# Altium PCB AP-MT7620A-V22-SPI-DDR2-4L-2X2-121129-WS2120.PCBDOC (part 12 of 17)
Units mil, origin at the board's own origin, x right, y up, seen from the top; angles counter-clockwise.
Board outline 7316 x 4279 mil, 4 copper layers (Top, Inner Layer 2, Inner Layer 3, Bottom), stack 35.4 mil thick; 640 components, 473 nets, 2041 pads, 2358 vias.
Unrouted connection lines stored in the file: 11.
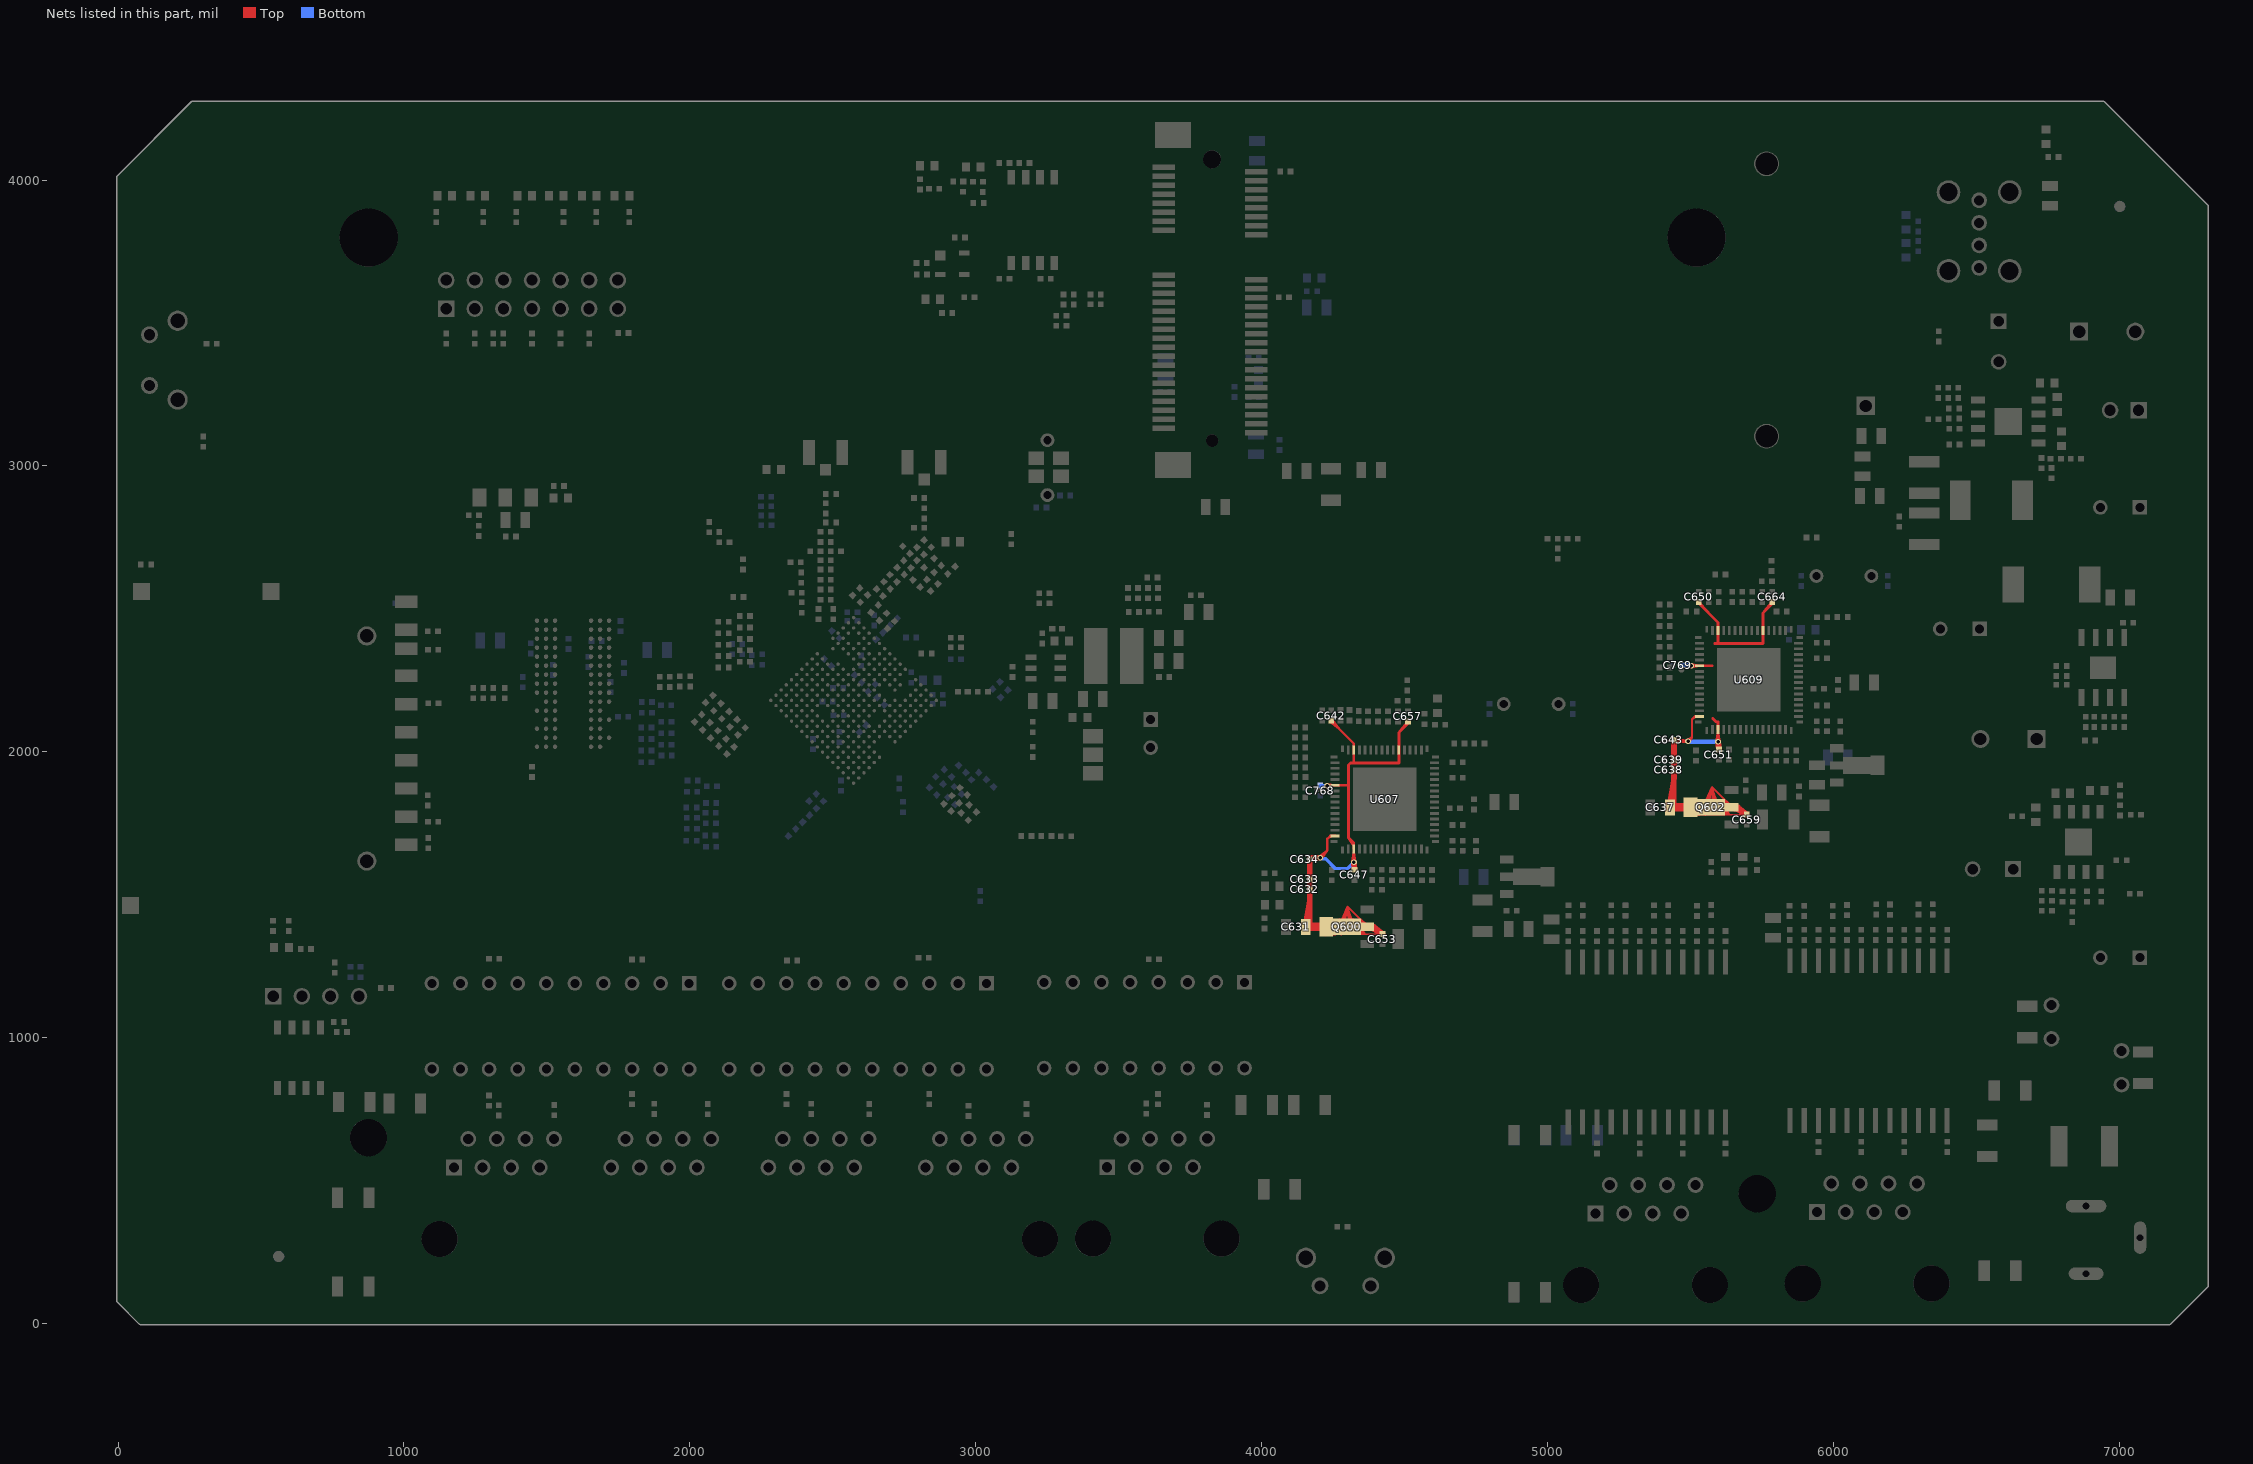
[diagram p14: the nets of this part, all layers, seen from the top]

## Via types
v1: diameter 20, hole 12, Top to Bottom, 2117 vias
v2: diameter 16, hole 8, Top to Bottom, 241 vias

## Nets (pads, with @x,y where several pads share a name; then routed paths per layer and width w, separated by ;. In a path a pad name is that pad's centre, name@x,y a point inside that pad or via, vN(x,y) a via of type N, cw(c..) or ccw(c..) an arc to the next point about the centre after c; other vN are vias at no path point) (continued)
P_DVDD_IP1001: C631.1 C632.1 C633.1 C634.1 C642.1 C647.1 C653.2 C657.1 C768.1 Q600.2 Q600.4 Q600.5 U607.3 U607.38 U607.46 U607.54 U607.63 | length 26663.2
  Top w4: v1@4228.67,1885.43 U607.54@4246.38,1886.13 ; v1@4228.98,1889.47 U607.54@4246.38,1886.13 ; v1@4229.33,1885.48 U607.54@4246.93,1883.26 ; v1@4229.48,1877.48 U607.54@4246.99,1880.34 ; v1@4229.62,1877.49 U607.54@4253.28,1881.48 ; v1@4229.62,1885.46 U607.54@4253.28,1881.48 ; v1@4229.99,1885.42 U607.54@4246.99,1880.34 ; v1@4230.13,1877.57 U607.54@4246.93,1883.26 ; v1@4230.29,1889.41 U607.54@4246.93,1883.26 ; v1@4230.62,1889.37 U607.54@4253.28,1881.48 ; v1@4230.76,1877.76 U607.54@4246.38,1886.13 ; v1@4231.58,1889.14 U607.54@4246.99,1880.34 ; v1@4231.86,1873.91 U607.54@4246.93,1883.26 ; v1@4233.07,1874.43 U607.54@4246.38,1886.13 ; U607.54@4268.53,1880.34 4285.55,1881.48 ; U607.54@4268.59,1883.26 4285.55,1881.48 ; U607.54@4269.14,1886.13 4285.55,1881.48 ; 4301.99,1881.48 v1(4229.28,1881.48) ; v1(4229.28,1881.48) U607.54@4246.99,1880.34 ; v1(4229.28,1881.48) U607.54@4246.38,1886.13 ; v1(4229.28,1881.48) U607.54@4246.93,1883.26 ; v1@4229.99,1881.48 U607.54@4246.99,1880.34 ; v1@4229.99,1881.48 U607.54@4246.38,1886.13 ; v1@4229.99,1881.48 U607.54@4246.93,1883.26 ; U607.54@4246.99,1880.34 4230.58,1873.58 U607.54@4253.28,1881.48
  Top w5: Q600.2@4220.32,1367.38 Q600.5@4274.82,1362.05 ; Q600.2@4221.05,1372.4 Q600.5@4274.82,1362.05 ; Q600.2@4222.23,1377.3 Q600.5@4274.82,1362.05 ; Q600.2@4223.85,1382.05 Q600.5@4274.82,1362.05 ; Q600.5@4259.95,1368.21 Q600.2@4240.45,1404.67 ; Q600.5@4261.05,1408.85 Q600.2@4230.97,1366.34 ; Q600.5@4262.55,1366.09 Q600.2@4236.65,1401.31 ; Q600.5@4262.76,1410.16 Q600.2@4230.08,1370.66 ; Q600.5@4264.4,1370.97 Q600.2@4240.45,1404.67 ; Q600.5@4264.69,1411.4 Q600.2@4229.44,1375.21 ; Q600.5@4265.09,1405.68 Q600.2@4230.97,1366.34 ; Q600.5@4265.19,1364.42 Q600.2@4233.2,1397.63 ; Q600.5@4266.55,1369.42 Q600.2@4236.65,1401.31 ; Q600.5@4266.56,1406.68 Q600.2@4230.08,1370.66 ; Q600.5@4266.87,1412.54 Q600.2@4229.11,1379.99 ; Q600.5@4267.82,1363.14 Q600.2@4230.12,1393.67 ; Q600.5@4268.2,1407.62 Q600.2@4229.44,1375.21 ; Q600.5@4268.4,1374.2 Q600.2@4240.45,1404.67 ; Q600.5@4268.72,1368.22 Q600.2@4233.2,1397.63 ; Q600.5@4268.77,1402.16 Q600.2@4230.97,1366.34 ; Q600.5@4269.95,1402.89 Q600.2@4230.08,1370.66 ; Q600.5@4270.03,1408.46 Q600.2@4229.11,1379.99 ; Q600.5@4270.08,1373.14 Q600.2@4236.65,1401.31 ; Q600.5@4270.13,1413.81 Q600.2@4229.23,1386.65 ; Q600.5@4270.85,1367.32 Q600.2@4230.12,1393.67 ; Q600.5@4271.24,1361.96 Q600.2@4226.63,1388.05 ; Q600.5@4271.26,1403.55 Q600.2@4229.44,1375.21 ; Q600.5@4271.24,1414.14 Q600.2@4226.63,1388.05 ; Q600.5@4271.61,1361.86 Q600.2@4229.23,1386.65 ; Q600.5@4271.58,1393.8 4299.95,1460.55 ; Q600.5@4271.75,1372.33 Q600.2@4233.2,1397.63 ; Q600.5@4271.92,1377.86 Q600.2@4240.45,1404.67 ; Q600.5@4272.06,1398.33 Q600.2@4230.97,1366.34 ; Q600.5@4272.72,1404.14 Q600.2@4229.11,1379.99 ; Q600.5@4272.75,1409.37 Q600.2@4229.23,1386.65 ; Q600.5@4272.93,1398.81 Q600.2@4230.08,1370.66 ; Q600.5@4273.12,1377.2 Q600.2@4236.65,1401.31 ; Q600.5@4273.39,1371.75 Q600.2@4230.12,1393.67 ; Q600.5@4273.61,1409.57 Q600.2@4226.63,1388.05 ; Q600.5@4273.83,1414.71 Q600.2@4230.12,1393.67 ; Q600.5@4273.89,1399.24 Q600.2@4229.44,1375.21 ; Q600.5@4273.98,1366.45 Q600.2@4229.23,1386.65 ; Q600.5@4274.29,1376.71 Q600.2@4233.2,1397.63 ; Q600.5@4274.87,1404.73 Q600.2@4229.23,1386.65 ; Q600.5@4274.94,1381.88 Q600.2@4240.45,1404.67 ; Q600.5@4274.95,1394.23 Q600.2@4230.97,1366.34 ; Q600.5@4274.94,1399.6 Q600.2@4229.11,1379.99 ; Q600.5@4275.28,1361.19 Q600.2@4229.11,1379.99 ; Q600.5@4275.44,1376.37 Q600.2@4230.12,1393.67 ; Q600.5@4275.47,1394.48 Q600.2@4230.08,1370.66 ; Q600.5@4275.5,1371.26 Q600.2@4226.63,1388.05 ; Q600.5@4275.5,1404.84 Q600.2@4226.63,1388.05 ; Q600.5@4275.64,1381.55 Q600.2@4236.65,1401.31 ; Q600.5@4275.82,1409.94 Q600.2@4230.12,1393.67 ; Q600.5@4275.83,1371.2 Q600.2@4229.23,1386.65 ; Q600.5@4275.92,1414.97 Q600.2@4233.2,1397.63 ; Q600.5@4276.05,1394.71 Q600.2@4229.44,1375.21 ; Q600.5@4276.32,1391.98 4299.95,1460.55 ; Q600.5@4276.33,1381.31 Q600.2@4233.2,1397.63 ; Q600.5@4276.49,1399.94 Q600.2@4229.23,1386.65 ; Q600.5@4276.68,1394.89 Q600.2@4229.11,1379.99 ; Q600.5@4276.91,1376.1 Q600.2@4226.63,1388.05 ; Q600.5@4276.91,1400 Q600.2@4226.63,1388.05 ; Q600.5@4276.98,1366.06 Q600.2@4229.11,1379.99 ; Q600.5@4277.28,1405.05 Q600.2@4230.12,1393.67 ; Q600.5@4277.6,1395.04 Q600.2@4229.23,1386.65 ; Q600.5@4277.6,1410.07 Q600.2@4233.2,1397.63 ; Q600.5@4277.83,1381.04 Q600.2@4226.63,1388.05 ; Q600.5@4277.93,1361.03 Q600.2@4229.44,1375.21 ; Q600.5@4278.15,1371.02 Q600.2@4229.11,1379.99 ; Q600.5@4278.14,1415.08 Q600.2@4236.65,1401.31 ; Q600.5@4278.21,1400.08 Q600.2@4230.12,1393.67 ; Q600.5@4278.61,1395.07 Q600.2@4230.12,1393.67 ; Q600.5@4278.71,1405.07 Q600.2@4233.2,1397.63 ; Q600.5@4278.8,1376.03 Q600.2@4229.11,1379.99 ; Q600.5@4278.95,1381.05 Q600.2@4229.11,1379.99 ; Q600.5@4279.12,1366.04 Q600.2@4229.44,1375.21 ; Q600.5@4279.24,1395.02 Q600.2@4233.2,1397.63 ; Q600.5@4279.25,1400.04 Q600.2@4233.2,1397.63 ; Q600.5@4279.48,1410.05 Q600.2@4236.65,1401.31 ; Q600.5@4279.61,1381.15 Q600.2@4229.44,1375.21 ; Q600.5@4279.8,1371.09 Q600.2@4229.44,1375.21 ; Q600.5@4279.89,1394.9 Q600.2@4236.65,1401.31 ; Q600.5@4279.96,1376.14 Q600.2@4229.44,1375.21 ; Q600.5@4280.21,1404.97 Q600.2@4236.65,1401.31 ; Q600.5@4280.23,1381.29 Q600.2@4230.08,1370.66 ; Q600.5@4280.34,1399.9 Q600.2@4236.65,1401.31 ; Q600.5@4280.45,1361.11 Q600.2@4230.08,1370.66 ; Q600.5@4280.49,1414.99 Q600.2@4240.45,1404.67 ; Q600.5@4280.57,1394.7 Q600.2@4240.45,1404.67 ; Q600.5@4280.8,1381.48 Q600.2@4230.97,1366.34 ; Q600.5@4281.03,1376.33 Q600.2@4230.08,1370.66 ; Q600.5@4281.15,1366.21 Q600.2@4230.08,1370.66 ; Q600.5@4281.14,1390.51 4299.95,1460.55 ; Q600.5@4281.34,1371.3 Q600.2@4230.08,1370.66 ; Q600.5@4281.47,1409.85 Q600.2@4240.45,1404.67 ; Q600.5@4281.49,1399.65 Q600.2@4240.45,1404.67 ; Q600.5@4281.79,1404.72 Q600.2@4240.45,1404.67 ; Q600.5@4282.02,1376.61 Q600.2@4230.97,1366.34 ; Q600.5@4282.81,1361.4 Q600.2@4230.97,1366.34 ; Q600.5@4282.78,1371.62 Q600.2@4230.97,1366.34 ; Q600.5@4283.05,1366.54 Q600.2@4230.97,1366.34 ; Q600.5@4286.04,1389.37 4299.95,1460.55 ; Q600.5@4290.98,1388.58 4299.95,1460.55 ; Q600.5@4297.99,1388.05 4302.94,1393 4392.04,1393 4409,1376.04 ; Q600.5@4305.02,1388.2 4299.95,1460.55 ; Q600.5@4310,1388.72 4299.95,1460.55 ; Q600.5@4310.81,1361.91 4363.51,1362.05 ; Q600.5@4311.05,1367.04 4363.51,1362.05 ; Q600.5@4311.78,1372.08 4363.51,1362.05 ; Q600.5@4312.97,1376.98 4363.51,1362.05 ; Q600.5@4314.62,1381.72 4363.51,1362.05 ; Q600.5@4314.95,1389.59 4299.95,1460.55 ; Q600.5@4316.06,1399.97 Q600.4@4359.05,1399.72 ; Q600.5@4316.14,1376.12 Q600.4@4355.24,1377.15 ; Q600.5@4316.33,1381.15 Q600.4@4355.24,1377.15 ; Q600.5@4316.33,1394.95 Q600.4@4359.05,1399.72 ; Q600.5@4316.39,1405.03 Q600.4@4359.05,1399.72 ; Q600.5@4316.6,1371.06 Q600.4@4355.24,1377.15 ; Q600.5@4317.17,1381.04 Q600.4@4357.56,1381.64 ; Q600.5@4317.33,1410.07 Q600.4@4359.05,1399.72 ; Q600.5@4317.39,1400.07 Q600.4@4368.59,1395.25 ; Q600.5@4317.45,1395.07 Q600.4@4362.27,1393 ; Q600.5@4317.49,1400.08 Q600.4@4359.77,1394.71 ; Q600.5@4317.55,1376.02 Q600.4@4357.56,1381.64 ; Q600.5@4317.66,1395.08 Q600.4@4365,1391.7 ; Q600.5@4317.7,1381.02 Q600.4@4375.8,1384.71 ; Q600.5@4317.74,1366.02 Q600.4@4355.24,1377.15 ; Q600.5@4317.79,1381.02 Q600.4@4348.13,1385.03 ; Q600.5@4317.92,1381.03 Q600.4@4353.13,1385.77 ; Q600.5@4317.96,1400.07 Q600.4@4362.27,1393 ; Q600.5@4318.11,1405.07 Q600.4@4368.59,1395.25 ; Q600.5@4318.23,1376.04 Q600.4@4375.8,1384.71 ; Q600.5@4318.28,1400.06 Q600.4@4365,1391.7 ; Q600.5@4318.43,1405.06 Q600.4@4359.77,1394.71 ; Q600.5@4318.5,1395.03 Q600.4@4375.8,1384.71 ; Q600.5@4318.58,1371.05 Q600.4@4357.56,1381.64 ; Q600.5@4318.73,1381.1 Q600.4@4365,1391.7 ; Q600.5@4318.82,1394.98 Q600.4@4353.13,1385.77 ; Q600.5@4318.86,1376.08 Q600.4@4348.13,1385.03 ; Q600.5@4318.89,1415.05 Q600.4@4359.05,1399.72 ; Q600.5@4318.95,1376.09 Q600.4@4353.13,1385.77 ; Q600.5@4319,1381.15 Q600.4@4362.27,1393 ; Q600.5@4319.04,1405.02 Q600.4@4362.27,1393 ; Q600.5@4319.13,1381.18 Q600.4@4368.59,1395.25 ; Q600.5@4319.17,1394.92 Q600.4@4348.13,1385.03 ; Q600.5@4319.19,1371.09 Q600.4@4375.8,1384.71 ; Q600.5@4319.34,1381.22 Q600.4@4359.77,1394.71 ; Q600.5@4319.33,1410.01 Q600.4@4368.59,1395.25 ; Q600.5@4319.39,1394.87 Q600.4@4357.56,1381.64 ; Q600.5@4319.43,1404.99 Q600.4@4365,1391.7 ; Q600.5@4319.57,1361.09 Q600.4@4355.24,1377.15 ; Q600.5@4319.6,1399.92 Q600.4@4375.8,1384.71 ; Q600.5@4319.84,1390.8 4299.95,1460.55 ; Q600.5@4319.97,1409.96 Q600.4@4359.77,1394.71 ; Q600.5@4320.11,1376.27 Q600.4@4365,1391.7 ; Q600.5@4320.13,1381.46 Q600.4@4359.05,1399.72 ; Q600.5@4320.24,1366.17 Q600.4@4357.56,1381.64 ; Q600.5@4320.23,1394.6 Q600.4@4355.24,1377.15 ; Q600.5@4320.47,1399.75 Q600.4@4353.13,1385.77 ; Q600.5@4320.59,1366.22 Q600.4@4375.8,1384.71 ; Q600.5@4320.59,1376.38 Q600.4@4362.27,1393 ; Q600.5@4320.69,1371.29 Q600.4@4353.13,1385.77 ; Q600.5@4320.69,1409.87 Q600.4@4362.27,1393 ; Q600.5@4320.74,1376.42 Q600.4@4368.59,1395.25 ; Q600.5@4320.78,1371.31 Q600.4@4348.13,1385.03 ; Q600.5@4321.06,1414.87 Q600.4@4368.59,1395.25 ; Q600.5@4321.13,1409.81 Q600.4@4365,1391.7 ; Q600.5@4321.21,1376.55 Q600.4@4359.77,1394.71 ; Q600.5@4321.19,1399.55 Q600.4@4348.13,1385.03 ; Q600.5@4321.33,1399.51 Q600.4@4357.56,1381.64 ; Q600.5@4321.54,1393.92 4363.51,1362.05 ; Q600.5@4322.01,1371.58 Q600.4@4365,1391.7 ; Q600.5@4322.13,1414.71 Q600.4@4359.77,1394.71 ; Q600.5@4322.43,1361.44 Q600.4@4375.8,1384.71 ; Q600.5@4322.56,1361.47 Q600.4@4357.56,1381.64 ; Q600.5@4322.53,1377.04 Q600.4@4359.05,1399.72 ; Q600.5@4322.73,1371.79 Q600.4@4362.27,1393 ; Q600.5@4322.76,1398.95 Q600.4@4355.24,1377.15 ; Q600.5@4322.82,1371.82 Q600.4@4368.59,1395.25 ; Q600.5@4322.81,1404.29 Q600.4@4353.13,1385.77 ; Q600.5@4322.92,1414.56 Q600.4@4362.27,1393 ; Q600.5@4323.08,1409.4 Q600.4@4375.8,1384.71 ; Q600.5@4323.15,1366.71 Q600.4@4353.13,1385.77 ; Q600.5@4323.36,1414.47 Q600.4@4365,1391.7 ; Q600.5@4323.54,1366.82 Q600.4@4348.13,1385.03 ; Q600.5@4323.64,1372.1 Q600.4@4359.77,1394.71 ; Q600.5@4323.86,1403.91 Q600.4@4357.56,1381.64 ; Q600.5@4324,1403.86 Q600.4@4348.13,1385.03 ; Q600.5@4324.42,1367.08 Q600.4@4365,1391.7 ; Q600.5@4324.67,1392.36 4299.95,1460.55 ; Q600.5@4324.76,1397.77 4363.51,1362.05 ; Q600.5@4325.36,1367.41 Q600.4@4368.59,1395.25 ; Q600.5@4325.41,1367.42 Q600.4@4362.27,1393 ; Q600.5@4325.45,1372.9 Q600.4@4359.05,1399.72 ; Q600.5@4325.45,1413.94 Q600.4@4375.8,1384.71 ; Q600.5@4325.87,1402.98 Q600.4@4355.24,1377.15 ; Q600.5@4325.83,1408.51 Q600.4@4353.13,1385.77 ; Q600.5@4326.33,1362.45 Q600.4@4353.13,1385.77 ; Q600.5@4326.62,1367.92 Q600.4@4359.77,1394.71 ; Q600.5@4326.97,1408.02 Q600.4@4357.56,1381.64 ; Q600.5@4327.16,1362.74 Q600.4@4348.13,1385.03 ; Q600.5@4327.34,1362.81 Q600.4@4365,1391.7 ; Q600.5@4327.59,1407.72 Q600.4@4348.13,1385.03 ; Q600.5@4328.36,1363.22 Q600.4@4368.59,1395.25 ; Q600.5@4328.36,1401.31 4363.51,1362.05 ; Q600.5@4328.61,1363.33 Q600.4@4362.27,1393 ; Q600.5@4328.89,1369.09 Q600.4@4359.05,1399.72 ; Q600.5@4329.52,1406.62 Q600.4@4355.24,1377.15 ; Q600.5@4329.54,1412.34 Q600.4@4353.13,1385.77 ; Q600.5@4330.15,1364.07 Q600.4@4359.77,1394.71 ; Q600.5@4330.64,1411.76 Q600.4@4357.56,1381.64 ; Q600.5@4331.94,1411.01 Q600.4@4348.13,1385.03 ; Q600.5@4332.31,1404.51 4363.51,1362.05 ; Q600.5@4332.82,1365.66 Q600.4@4359.05,1399.72 ; Q600.5@4333.71,1409.8 Q600.4@4355.24,1377.15 ; Q600.5@4336.59,1407.35 4363.51,1362.05 ; C653.2@4416.91,1358.66 4409,1376.04 ; C653.2@4421.57,1370.41 4397.95,1362.05 ; C653.2@4422.16,1355.6 4397.95,1362.05 ; C653.2@4426.91,1369.44 4409,1376.04 ; Q600.2@4223.86,1371.71 Q600.5@4252.63,1362.05 ; Q600.2@4223.86,1371.71 Q600.5@4252.63,1362.05 ; Q600.2@4223.86,1371.71 4279.7,1361.06 Q600.2@4223.86,1371.71 ; Q600.2@4223.86,1371.71 4264.61,1411.35 Q600.2@4223.86,1371.71 ; Q600.2@4223.86,1371.71 4280.43,1366.12 Q600.2@4223.86,1371.71 ; Q600.2@4223.86,1371.71 4268.01,1407.52 Q600.2@4223.86,1371.71 ; Q600.2@4223.86,1371.71 4280.7,1371.19 Q600.2@4223.86,1371.71 ; Q600.2@4223.86,1371.71 4271.02,1403.44 Q600.2@4223.86,1371.71 ; Q600.2@4223.86,1371.71 4280.52,1376.23 Q600.2@4223.86,1371.71 ; Q600.2@4223.86,1371.71 4273.65,1399.14 Q600.2@4223.86,1371.71 ; Q600.2@4223.86,1371.71 4279.9,1381.21 Q600.2@4223.86,1371.71 ; Q600.2@4223.86,1371.71 4275.87,1394.64 Q600.2@4223.86,1371.71 ; Q600.2@4225.25,1366.39 4282.33,1361.32 Q600.2@4225.25,1366.39 ; Q600.2@4225.25,1366.39 4262.48,1409.96 Q600.2@4225.25,1366.39 ; Q600.2@4225.25,1366.39 4282.56,1366.44 Q600.2@4225.25,1366.39 ; Q600.2@4225.25,1366.39 4266.21,1406.46 Q600.2@4225.25,1366.39 ; Q600.2@4225.25,1366.39 4282.33,1371.5 Q600.2@4225.25,1366.39 ; Q600.2@4225.25,1366.39 4269.6,1402.68 Q600.2@4225.25,1366.39 ; Q600.2@4225.25,1366.39 4281.66,1376.5 Q600.2@4225.25,1366.39 ; Q600.2@4225.25,1366.39 4272.62,1398.65 Q600.2@4225.25,1366.39 ; Q600.2@4225.25,1366.39 4280.56,1381.39 Q600.2@4225.25,1366.39 ; Q600.2@4225.25,1366.39 4275.25,1394.38 Q600.2@4225.25,1366.39 ; Q600.2@4226.63,1377.72 Q600.5@4252.63,1362.05 ; Q600.2@4226.63,1377.72 Q600.5@4252.63,1362.05 ; Q600.2@4226.63,1377.72 4276.63,1361.07 Q600.2@4226.63,1377.72 ; Q600.2@4226.63,1377.72 4266.39,1412.31 Q600.2@4226.63,1377.72 ; Q600.2@4226.63,1377.72 4278.02,1366.02 Q600.2@4226.63,1377.72 ; Q600.2@4226.63,1377.72 4269.57,1408.27 Q600.2@4226.63,1377.72 ; Q600.2@4226.63,1377.72 4278.9,1371.03 Q600.2@4226.63,1377.72 ; Q600.2@4226.63,1377.72 4272.31,1403.99 Q600.2@4226.63,1377.72 ; Q600.2@4226.63,1377.72 4279.3,1376.06 Q600.2@4226.63,1377.72 ; Q600.2@4226.63,1377.72 4274.62,1399.5 Q600.2@4226.63,1377.72 ; Q600.2@4226.63,1377.72 4279.22,1381.08 Q600.2@4226.63,1377.72 ; Q600.2@4226.63,1377.72 4276.47,1394.83 Q600.2@4226.63,1377.72 ; Q600.2@4226.63,1388.05 Q600.5@4252.63,1362.05 ; Q600.2@4226.63,1388.05 Q600.5@4274.82,1362.05 ; Q600.2@4226.63,1388.05 Q600.5@4273.61,1366.53 ; Q600.2@4226.63,1388.05 Q600.5@4277.83,1395.06 ; Q600.2@4227.97,1361.75 4284.76,1361.81 Q600.2@4227.97,1361.75 ; Q600.2@4227.97,1361.75 4260.45,1408.34 Q600.2@4227.97,1361.75 ; Q600.2@4227.97,1361.75 4284.53,1366.92 Q600.2@4227.97,1361.75 ; Q600.2@4227.97,1361.75 4264.51,1405.22 Q600.2@4227.97,1361.75 ; Q600.2@4227.97,1361.75 4283.84,1371.95 Q600.2@4227.97,1361.75 ; Q600.2@4227.97,1361.75 4268.25,1401.79 Q600.2@4227.97,1361.75 ; Q600.2@4227.97,1361.75 4282.71,1376.86 Q600.2@4227.97,1361.75 ; Q600.2@4227.97,1361.75 4271.64,1398.06 Q600.2@4227.97,1361.75 ; Q600.2@4227.97,1361.75 4281.17,1381.63 Q600.2@4227.97,1361.75 ; Q600.2@4227.97,1361.75 4274.67,1394.07 Q600.2@4227.97,1361.75 ; Q600.2@4229.23,1386.65 Q600.5@4277.17,1376.08 ; Q600.2@4229.23,1386.65 Q600.5@4278,1381.03 ; Q600.2@4230.12,1393.67 Q600.5@4274.82,1362.05 ; Q600.2@4230.12,1393.67 Q600.5@4276.99,1381.15 ; Q600.2@4230.64,1382.98 Q600.5@4252.63,1362.05 ; Q600.2@4230.64,1382.98 Q600.5@4252.63,1362.05 ; Q600.2@4230.64,1382.98 4273.47,1361.46 Q600.2@4230.64,1382.98 ; Q600.2@4230.64,1382.98 4267.98,1413.03 Q600.2@4230.64,1382.98 ; Q600.2@4230.64,1382.98 4275.54,1366.2 Q600.2@4230.64,1382.98 ; Q600.2@4230.64,1382.98 4271,1408.83 Q600.2@4230.64,1382.98 ; Q600.2@4230.64,1382.98 4277.07,1371.07 Q600.2@4230.64,1382.98 ; Q600.2@4230.64,1382.98 4273.52,1404.39 Q600.2@4230.64,1382.98 ; Q600.2@4230.64,1382.98 4278.07,1376.02 Q600.2@4230.64,1382.98 ; Q600.2@4230.64,1382.98 4275.54,1399.76 Q600.2@4230.64,1382.98 ; Q600.2@4230.64,1382.98 4278.53,1381.03 Q600.2@4230.64,1382.98 ; Q600.2@4230.64,1382.98 4277.05,1394.96 Q600.2@4230.64,1382.98 ; Q600.2@4231.44,1358.07 4286.9,1362.43 Q600.2@4231.44,1358.07 ; Q600.2@4231.44,1358.07 4258.65,1406.6 Q600.2@4231.44,1358.07 ; Q600.2@4231.44,1358.07 4286.27,1367.51 Q600.2@4231.44,1358.07 ; Q600.2@4231.44,1358.07 4263,1403.89 Q600.2@4231.44,1358.07 ; Q600.2@4231.44,1358.07 4285.18,1372.47 Q600.2@4231.44,1358.07 ; Q600.2@4231.44,1358.07 4267.04,1400.82 Q600.2@4231.44,1358.07 ; Q600.2@4231.44,1358.07 4283.65,1377.28 Q600.2@4231.44,1358.07 ; Q600.2@4231.44,1358.07 4270.77,1397.42 Q600.2@4231.44,1358.07 ; Q600.2@4231.44,1358.07 4281.71,1381.9 Q600.2@4231.44,1358.07 ; Q600.2@4231.44,1358.07 4274.15,1393.72 Q600.2@4231.44,1358.07 ; Q600.2@4233.2,1397.63 Q600.5@4274.82,1362.05 ; Q600.2@4234.42,1386.33 Q600.5@4252.63,1362.05 ; Q600.2@4234.42,1386.33 Q600.5@4252.63,1362.05 ; Q600.2@4234.42,1386.33 4271,1362.03 Q600.2@4234.42,1386.33 ; Q600.2@4234.42,1386.33 4268.99,1413.42 Q600.2@4234.42,1386.33 ; Q600.2@4234.42,1386.33 Q600.5@4273.62,1366.53 ; Q600.2@4234.42,1386.33 4271.95,1409.14 Q600.2@4234.42,1386.33 ; Q600.2@4234.42,1386.33 4275.66,1371.23 Q600.2@4234.42,1386.33 ; Q600.2@4234.42,1386.33 4274.35,1404.61 Q600.2@4234.42,1386.33 ; Q600.2@4234.42,1386.33 Q600.5@4277.13,1376.08 ; Q600.2@4234.42,1386.33 4276.19,1399.89 Q600.2@4234.42,1386.33 ; Q600.2@4234.42,1386.33 Q600.5@4278.02,1381.03 ; Q600.2@4234.42,1386.33 4277.47,1395.03 Q600.2@4234.42,1386.33 ; Q600.2@4234.42,1386.33 Q600.5@4273.62,1366.53 ; Q600.2@4234.42,1386.33 Q600.5@4277.13,1376.08 ; Q600.2@4234.42,1386.33 Q600.5@4278.02,1381.03 ; Q600.2@4236.65,1401.31 Q600.5@4274.82,1362.05 ; Q600.2@4238.77,1389.06 Q600.5@4252.63,1362.05 ; Q600.2@4238.77,1389.06 Q600.5@4252.63,1362.05 ; Q600.2@4238.77,1389.06 4268.43,1362.89 Q600.2@4238.77,1389.06 ; Q600.2@4238.77,1389.06 4269.72,1413.68 Q600.2@4238.77,1389.06 ; Q600.2@4238.77,1389.06 4271.63,1367.06 Q600.2@4238.77,1389.06 ; Q600.2@4238.77,1389.06 4272.71,1409.36 Q600.2@4238.77,1389.06 ; Q600.2@4238.77,1389.06 4274.22,1371.52 Q600.2@4238.77,1389.06 ; Q600.2@4238.77,1389.06 4275.06,1404.77 Q600.2@4238.77,1389.06 ; Q600.2@4238.77,1389.06 4276.17,1376.21 Q600.2@4238.77,1389.06 ; Q600.2@4238.77,1389.06 4276.78,1399.98 Q600.2@4238.77,1389.06 ; Q600.2@4238.77,1389.06 4277.5,1381.07 Q600.2@4238.77,1389.06 ; Q600.2@4238.77,1389.06 Q600.5@4277.86,1395.06 ; Q600.2@4238.77,1389.06 Q600.5@4277.86,1395.06 ; Q600.2@4240.45,1404.67 Q600.5@4274.82,1362.05 ; Q600.2@4243.65,1391.04 Q600.5@4252.63,1362.05 ; Q600.2@4243.65,1391.04 Q600.5@4252.63,1362.05 ; Q600.2@4243.65,1391.04 4265.7,1364.14 Q600.2@4243.65,1391.04 ; Q600.2@4243.65,1391.04 4269.99,1413.77 Q600.2@4243.65,1391.04 ; Q600.2@4243.65,1391.04 4269.56,1367.83 Q600.2@4243.65,1391.04 ; Q600.2@4243.65,1391.04 4273.16,1409.47 Q600.2@4243.65,1391.04 ; Q600.2@4243.65,1391.04 4272.73,1371.96 Q600.2@4243.65,1391.04 ; Q600.2@4243.65,1391.04 4275.57,1404.86 Q600.2@4243.65,1391.04 ; Q600.2@4243.65,1391.04 4275.21,1376.43 Q600.2@4243.65,1391.04 ; Q600.2@4243.65,1391.04 4277.25,1400.03 Q600.2@4243.65,1391.04 ; Q600.2@4243.65,1391.04 Q600.5@4277,1381.15 ; Q600.2@4243.65,1391.04 4278.2,1395.08 Q600.2@4243.65,1391.04 ; Q600.2@4243.65,1391.04 Q600.5@4277,1381.15 ; Q600.5@4252.63,1362.05 C653.2@4422.99,1362.05 ; Q600.5@4252.63,1362.05 4222.8,1356.44 Q600.5@4252.63,1362.05 ; Q600.5@4252.63,1362.05 4222.28,1361.68 Q600.5@4252.63,1362.05 ; Q600.5@4252.63,1362.05 4222.65,1366.8 Q600.5@4252.63,1362.05 ; 4299.95,1460.55 4384.46,1376.04 4409,1376.04 ; Q600.5@4321.15,1404.72 Q600.4@4359.41,1388.05 ; Q600.5@4321.15,1404.72 Q600.4@4359.41,1388.05 ; Q600.5@4321.13,1404.72 Q600.4@4375.8,1384.71 ; Q600.5@4330.13,1393 Q600.4@4355.24,1377.15 ; Q600.5@4330.13,1393 Q600.4@4359.05,1399.72 ; Q600.5@4330.13,1393 Q600.4@4357.56,1381.64 ; Q600.5@4330.13,1393 Q600.4@4359.77,1394.71 ; Q600.5@4330.13,1393 Q600.4@4359.41,1388.05 ; Q600.5@4346.4,1414.11 Q600.4@4348.13,1385.03 ; Q600.5@4346.4,1414.11 Q600.4@4368.59,1395.25 ; Q600.5@4346.4,1414.11 Q600.4@4353.13,1385.77 ; Q600.5@4346.4,1414.11 Q600.4@4365,1391.7 ; Q600.5@4346.4,1414.11 Q600.4@4359.41,1388.05 ; Q600.4@4359.41,1388.05 4326.43,1413.62 Q600.4@4359.41,1388.05 ; Q600.4@4359.41,1388.05 4326.43,1362.48 Q600.4@4359.41,1388.05 ; Q600.4@4359.41,1388.05 4323.49,1409.3 Q600.4@4359.41,1388.05 ; Q600.4@4359.41,1388.05 4323.49,1366.8 Q600.4@4359.41,1388.05 ; Q600.4@4359.41,1388.05 4321.15,1371.38 Q600.4@4359.41,1388.05 ; Q600.4@4359.41,1388.05 4319.41,1399.95 Q600.4@4359.41,1388.05 ; Q600.4@4359.41,1388.05 4319.41,1376.15 Q600.4@4359.41,1388.05 ; Q600.4@4359.41,1388.05 4318.27,1395.05 Q600.4@4359.41,1388.05 ; Q600.4@4359.41,1388.05 4318.27,1381.05 Q600.4@4359.41,1388.05 ; Q600.4@4359.77,1394.71 4317.15,1395.06 Q600.4@4368.59,1395.25 ; 4397.95,1362.05 C653.2@4422.99,1363.05 ; 4409,1376.04 C653.2@4422.99,1362.05 ; 4409,1376.04 4385.56,1397.89 4409,1376.04 ; 4409,1376.04 4376.96,1376.61 4409,1376.04 ; 4409,1376.04 4382.42,1393.94 4409,1376.04 ; 4409,1376.04 4377.45,1381.64 4409,1376.04 ; 4409,1376.04 4379.29,1388.05 4409,1376.04 ; 4409,1376.04 C653.2@4422.99,1363.05 ; C653.2@4422.99,1362.05 C653.2@4422.99,1363.05
  Top w8: v1@4201.13,1634.59 4230,1655 ; v1(4205,1630) 4230,1655 ; v1@4209.59,1626.13 4230,1655 ; v1@4229.61,1887.47 U607.54@4257.76,1882.93 ; v1@4229.7,1887.46 U607.54@4246.93,1883.26 ; v1@4230.22,1875.55 U607.54@4257.76,1882.93 ; v1@4230.89,1875.7 U607.54@4246.93,1883.26 ; C642.1@4240.02,2104.51 4270.42,2081.58 ; C642.1@4248.64,2112.81 4270.42,2081.58 ; U607.63@4257.76,1706.1 4240,1706.1 ; U607.54@4268.59,1883.26 4297.51,1883.26 ; 4303.99,1883.26 U607.54@4257.76,1883.26 U607.54@4257.76,1882.93 ; v1@4317,1614.23 C647.1@4319,1588.23 ; v1@4317.02,1614.45 U607.3@4322.72,1649.99 ; v1@4317.02,1614.5 4323,1650 v1@4328.98,1614.5 ; v1@4317.04,1613.33 C647.1@4323,1587 ; v1@4317.11,1612.85 C647.1@4325,1588 ; v1@4317.53,1611.54 C647.1@4330.89,1589.15 ; U607.3@4322.72,1660.82 4323,1660.54 v1(4323,1614) ; U607.46@4322.72,2007.28 4322.72,2029.28 ; U607.46@4322.72,2018.11 4322.72,2029.28 ; v1@4323,1621.07 U607.3@4322.72,1649.99 ; v1@4328.78,1612.4 C647.1@4319,1588.23 ; v1@4328.89,1615.15 C647.1@4330.89,1589.15 ; v1@4328.96,1613.33 C647.1@4323,1587 ; v1@4329,1613.77 C647.1@4325,1588 ; v1@4328.98,1614.55 U607.3@4322.72,1649.99 ; v1(4229.28,1881.48) v1@4229.28,1882.93 ; v1(4229.28,1881.48) U607.54@4257.76,1882.93 ; v1(4229.28,1881.48) U607.54@4246.93,1883.26 ; v1@4229.28,1882.93 U607.54@4257.76,1882.93 ; v1@4229.28,1882.93 U607.54@4246.93,1883.26 ; 4230,1655 4230,1696.1 ; 4230,1696.1 4240,1706.1 ; 4230,1696.1 U607.63@4246.93,1706.1 ; 4240,1706.1 U607.63@4246.93,1706.1 ; 4240,1706.1 U607.63@4246.93,1706.1 ; 4270.42,2081.58 C642.1@4244,2109 4244,2110 4243,2109 4322.72,2029.28 ; C647.1@4319,1588.23 v1(4323,1614) ; C647.1@4319,1588.23 v1(4323,1614) ; U607.3@4322.72,1649.99 v1(4323,1614) ; C647.1@4323,1587 v1(4323,1614) ; C647.1@4323,1587 4325,1587 C647.1@4325,1588 ; C647.1@4323,1587 v1(4323,1614) ; v1(4323,1614) C647.1@4330.89,1589.15 ; v1(4323,1614) C647.1@4325,1588
  Top w10: U607.3@4322.72,1660.82 4322.72,1681.33 ; 4322.72,1961.53 U607.46@4322.72,1996.45 ; U607.46@4322.72,2007.28 4322.72,1961.05 ; 4480.2,1961.53 U607.38@4480.2,1996.45 ; U607.38@4480.2,2018.11 4480.2,2053.03 ; 4484.28,2072.13 C657.1@4511.99,2106.05 ; C657.1@4512,2107.04 4512,2099.85 4480.2,2068.05 U607.38@4480.2,2007.28 4480.2,1961.05 4322.72,1961.05 ; 4305.79,1698.26 4304.31,1698.26 4304.31,1698.73 4303.99,1699.05 4303.99,1883.26 4303.99,1954.05 4310.99,1961.05 4322.72,1961.05 ; 4305.79,1698.26 4322.72,1681.33 ; 4305.79,1698.26 U607.3@4322.72,1671.65 ; U607.3@4322.72,1671.65 4322.72,1681.33 ; U607.3@4322.72,1671.65 4322.72,1681.33
  Top w20: C631.1@4154.44,1399.05 4168.99,1478.3 ; C631.1@4168.99,1388.05 C632.1@4168.99,1519.05 ; 4168.99,1449.05 C632.1@4168.99,1519.05 ; Q600.4@4369.35,1388.05 4370.35,1387.05 Q600.4@4392.99,1387.05 ; C632.1@4168.99,1519.05 C633.1@4168.99,1562 ; C632.1@4168.99,1519.05 C633.1@4168.99,1554.05 ; C633.1@4168.99,1554.05 C633.1@4168.99,1562 ; C633.1@4168.99,1554.05 C634.1@4168.99,1624.05 ; C633.1@4168.99,1554.05 C634.1@4168.99,1624.05 ; C633.1@4168.99,1562 C634.1@4168.99,1624.05 ; C633.1@4168.99,1562 C634.1@4168.99,1624.05 ; C634.1@4168.99,1624.05 C634.1@4174.94,1630 ; C634.1@4168.99,1624.05 v1(4205,1630) ; C634.1@4168.99,1624.05 v1(4205,1630) ; C634.1@4174.94,1630 v1(4205,1630) ; C634.1@4174.94,1630 v1(4205,1630) ; Q600.4@4392.99,1387.05 4408.02,1372.02 ; Q600.4@4392.99,1387.05 C653.2@4422.99,1363.05 ; 4408.02,1372.02 4379.29,1388.05 C653.2@4422.99,1363.05 ; 4408.02,1372.02 C653.2@4422.99,1363.05 ; 4408.02,1372.02 C653.2@4422.99,1363.05 ; 4408.02,1372.02 C653.2@4422.99,1363.05 ; 4408.07,1372.02 4418.04,1362.05 4422.99,1362.05 C653.2@4422.99,1363.05 ; 4408.07,1372.02 C653.2@4422.99,1363.05 ; 4408.07,1372.02 C653.2@4422.99,1363.05
  Top w30: C631.1@4168.99,1388.05 C631.1@4154.44,1388.05 Q600.2@4226.63,1388.05
  Bottom w12: C768.1@4205,1881.48 v1(4229.28,1881.48) ; C768.1@4205,1881.48 C768.1@4205,1882 ; C768.1@4205,1881.48 v1(4229.28,1881.48) ; C768.1@4205,1882 v1(4229.28,1881.48) ; C768.1@4205,1882 v1(4229.28,1881.48) ; 4224,1626 4205,1626 v1(4205,1630) 4224,1626 ; 4224,1626 4258,1592 4301,1592 ; 4301,1592 v1(4323,1614) 4301,1592
P_DVDD_IP1001-2: C637.1 C638.1 C639.1 C643.1 C650.1 C651.1 C659.2 C664.1 C769.1 Q602.2 Q602.4 Q602.5 U609.3 U609.38 U609.46 U609.54 U609.63 | length 26037.8
  Top w4.5: U609.3@5594.07,2089.32 5594.03,2100.55 ; U609.3@5596.72,2078.82 5594.03,2081.52 5594.03,2100.55 ; U609.3@5596.72,2089.65 5594.03,2100.55 ; U609.3@5599.22,2090.59 5594.03,2100.55
  Top w5: Q602.2@5494.32,1785.38 Q602.5@5548.82,1780.05 ; Q602.2@5495.05,1790.4 Q602.5@5548.82,1780.05 ; Q602.2@5496.23,1795.3 Q602.5@5548.82,1780.05 ; Q602.2@5497.85,1800.05 Q602.5@5548.82,1780.05 ; Q602.5@5533.95,1786.21 Q602.2@5514.45,1822.67 ; Q602.5@5535.05,1826.85 Q602.2@5504.97,1784.34 ; Q602.5@5536.55,1784.09 Q602.2@5510.65,1819.31 ; Q602.5@5536.76,1828.16 Q602.2@5504.08,1788.66 ; Q602.5@5538.4,1788.97 Q602.2@5514.45,1822.67 ; Q602.5@5538.69,1829.4 Q602.2@5503.44,1793.21 ; Q602.5@5539.09,1823.68 Q602.2@5504.97,1784.34 ; Q602.5@5539.19,1782.42 Q602.2@5507.2,1815.63 ; Q602.5@5540.55,1787.42 Q602.2@5510.65,1819.31 ; Q602.5@5540.56,1824.68 Q602.2@5504.08,1788.66 ; Q602.5@5540.87,1830.54 Q602.2@5503.11,1797.99 ; Q602.5@5541.82,1781.14 Q602.2@5504.12,1811.67 ; Q602.5@5542.2,1825.62 Q602.2@5503.44,1793.21 ; Q602.5@5542.4,1792.2 Q602.2@5514.45,1822.67 ; Q602.5@5542.72,1786.22 Q602.2@5507.2,1815.63 ; Q602.5@5542.77,1820.16 Q602.2@5504.97,1784.34 ; Q602.5@5543.95,1820.89 Q602.2@5504.08,1788.66 ; Q602.5@5544.03,1826.46 Q602.2@5503.11,1797.99 ; Q602.5@5544.08,1791.14 Q602.2@5510.65,1819.31 ; Q602.5@5544.13,1831.81 Q602.2@5503.23,1804.65 ; Q602.5@5544.85,1785.32 Q602.2@5504.12,1811.67 ; Q602.5@5545.24,1779.96 Q602.2@5500.63,1806.05 ; Q602.5@5545.26,1821.55 Q602.2@5503.44,1793.21 ; Q602.5@5545.24,1832.14 Q602.2@5500.63,1806.05 ; Q602.5@5545.61,1779.86 Q602.2@5503.23,1804.65 ; Q602.5@5545.58,1811.8 5573.95,1878.55 ; Q602.5@5545.75,1790.33 Q602.2@5507.2,1815.63 ; Q602.5@5545.92,1795.86 Q602.2@5514.45,1822.67 ; Q602.5@5546.06,1816.33 Q602.2@5504.97,1784.34 ; Q602.5@5546.72,1822.14 Q602.2@5503.11,1797.99 ; Q602.5@5546.75,1827.37 Q602.2@5503.23,1804.65 ; Q602.5@5546.93,1816.81 Q602.2@5504.08,1788.66 ; Q602.5@5547.12,1795.2 Q602.2@5510.65,1819.31 ; Q602.5@5547.39,1789.75 Q602.2@5504.12,1811.67 ; Q602.5@5547.61,1827.57 Q602.2@5500.63,1806.05 ; Q602.5@5547.83,1832.71 Q602.2@5504.12,1811.67 ; Q602.5@5547.89,1817.24 Q602.2@5503.44,1793.21 ; Q602.5@5547.98,1784.45 Q602.2@5503.23,1804.65 ; Q602.5@5548.29,1794.71 Q602.2@5507.2,1815.63 ; Q602.5@5548.87,1822.73 Q602.2@5503.23,1804.65 ; Q602.5@5548.94,1799.88 Q602.2@5514.45,1822.67 ; Q602.5@5548.95,1812.23 Q602.2@5504.97,1784.34 ; Q602.5@5548.94,1817.6 Q602.2@5503.11,1797.99 ; Q602.5@5549.28,1779.19 Q602.2@5503.11,1797.99 ; Q602.5@5549.44,1794.37 Q602.2@5504.12,1811.67 ; Q602.5@5549.47,1812.48 Q602.2@5504.08,1788.66 ; Q602.5@5549.5,1789.26 Q602.2@5500.63,1806.05 ; Q602.5@5549.5,1822.84 Q602.2@5500.63,1806.05 ; Q602.5@5549.64,1799.55 Q602.2@5510.65,1819.31 ; Q602.5@5549.82,1827.94 Q602.2@5504.12,1811.67 ; Q602.5@5549.83,1789.2 Q602.2@5503.23,1804.65 ; Q602.5@5549.92,1832.97 Q602.2@5507.2,1815.63 ; Q602.5@5550.05,1812.71 Q602.2@5503.44,1793.21 ; Q602.5@5550.32,1809.98 5573.95,1878.55 ; Q602.5@5550.33,1799.31 Q602.2@5507.2,1815.63 ; Q602.5@5550.49,1817.94 Q602.2@5503.23,1804.65 ; Q602.5@5550.68,1812.89 Q602.2@5503.11,1797.99 ; Q602.5@5550.91,1794.1 Q602.2@5500.63,1806.05 ; Q602.5@5550.91,1818 Q602.2@5500.63,1806.05 ; Q602.5@5550.98,1784.06 Q602.2@5503.11,1797.99 ; Q602.5@5551.28,1823.05 Q602.2@5504.12,1811.67 ; Q602.5@5551.6,1813.04 Q602.2@5503.23,1804.65 ; Q602.5@5551.6,1828.07 Q602.2@5507.2,1815.63 ; Q602.5@5551.83,1799.04 Q602.2@5500.63,1806.05 ; Q602.5@5551.93,1779.03 Q602.2@5503.44,1793.21 ; Q602.5@5552.15,1789.02 Q602.2@5503.11,1797.99 ; Q602.5@5552.14,1833.08 Q602.2@5510.65,1819.31 ; Q602.5@5552.21,1818.08 Q602.2@5504.12,1811.67 ; Q602.5@5552.61,1813.07 Q602.2@5504.12,1811.67 ; Q602.5@5552.71,1823.07 Q602.2@5507.2,1815.63 ; Q602.5@5552.8,1794.03 Q602.2@5503.11,1797.99 ; Q602.5@5552.95,1799.05 Q602.2@5503.11,1797.99 ; Q602.5@5553.12,1784.04 Q602.2@5503.44,1793.21 ; Q602.5@5553.24,1813.02 Q602.2@5507.2,1815.63 ; Q602.5@5553.25,1818.04 Q602.2@5507.2,1815.63 ; Q602.5@5553.48,1828.05 Q602.2@5510.65,1819.31 ; Q602.5@5553.61,1799.15 Q602.2@5503.44,1793.21 ; Q602.5@5553.8,1789.09 Q602.2@5503.44,1793.21 ; Q602.5@5553.89,1812.9 Q602.2@5510.65,1819.31 ; Q602.5@5553.96,1794.14 Q602.2@5503.44,1793.21 ; Q602.5@5554.21,1822.97 Q602.2@5510.65,1819.31 ; Q602.5@5554.23,1799.29 Q602.2@5504.08,1788.66 ; Q602.5@5554.34,1817.9 Q602.2@5510.65,1819.31 ; Q602.5@5554.45,1779.11 Q602.2@5504.08,1788.66 ; Q602.5@5554.49,1832.99 Q602.2@5514.45,1822.67 ; Q602.5@5554.57,1812.7 Q602.2@5514.45,1822.67 ; Q602.5@5554.8,1799.48 Q602.2@5504.97,1784.34 ; Q602.5@5555.03,1794.33 Q602.2@5504.08,1788.66 ; Q602.5@5555.15,1784.21 Q602.2@5504.08,1788.66 ; Q602.5@5555.14,1808.51 5573.95,1878.55 ; Q602.5@5555.34,1789.3 Q602.2@5504.08,1788.66 ; Q602.5@5555.47,1827.85 Q602.2@5514.45,1822.67 ; Q602.5@5555.49,1817.65 Q602.2@5514.45,1822.67 ; Q602.5@5555.79,1822.72 Q602.2@5514.45,1822.67 ; Q602.5@5556.02,1794.61 Q602.2@5504.97,1784.34 ; Q602.5@5556.81,1779.4 Q602.2@5504.97,1784.34 ; Q602.5@5556.78,1789.62 Q602.2@5504.97,1784.34 ; Q602.5@5557.05,1784.54 Q602.2@5504.97,1784.34 ; Q602.5@5560.04,1807.37 5573.95,1878.55 ; Q602.5@5564.98,1806.58 5573.95,1878.55 ; Q602.5@5571.99,1806.05 5576.94,1811 5666.04,1811 5683,1794.04 ; Q602.5@5579.02,1806.2 5573.95,1878.55 ; Q602.5@5584,1806.72 5573.95,1878.55 ; Q602.5@5584.81,1779.91 5637.51,1780.05 ; Q602.5@5585.05,1785.04 5637.51,1780.05 ; Q602.5@5585.78,1790.08 5637.51,1780.05 ; Q602.5@5586.97,1794.98 5637.51,1780.05 ; Q602.5@5588.62,1799.72 5637.51,1780.05 ; Q602.5@5588.95,1807.59 5573.95,1878.55 ; Q602.5@5590.06,1817.97 Q602.4@5633.05,1817.72 ; Q602.5@5590.14,1794.12 Q602.4@5629.24,1795.15 ; Q602.5@5590.33,1799.15 Q602.4@5629.24,1795.15 ; Q602.5@5590.33,1812.95 Q602.4@5633.05,1817.72 ; Q602.5@5590.39,1823.03 Q602.4@5633.05,1817.72 ; Q602.5@5590.6,1789.06 Q602.4@5629.24,1795.15 ; Q602.5@5591.17,1799.04 Q602.4@5631.56,1799.64 ; Q602.5@5591.33,1828.07 Q602.4@5633.05,1817.72 ; Q602.5@5591.39,1818.07 Q602.4@5642.59,1813.25 ; Q602.5@5591.45,1813.07 Q602.4@5636.27,1811 ; Q602.5@5591.49,1818.08 Q602.4@5633.77,1812.71 ; Q602.5@5591.55,1794.02 Q602.4@5631.56,1799.64 ; Q602.5@5591.66,1813.08 Q602.4@5639,1809.7 ; Q602.5@5591.7,1799.02 Q602.4@5649.8,1802.71 ; Q602.5@5591.74,1784.02 Q602.4@5629.24,1795.15 ; Q602.5@5591.79,1799.02 Q602.4@5622.13,1803.03 ; Q602.5@5591.92,1799.03 Q602.4@5627.13,1803.77 ; Q602.5@5591.96,1818.07 Q602.4@5636.27,1811 ; Q602.5@5592.11,1823.07 Q602.4@5642.59,1813.25 ; Q602.5@5592.23,1794.04 Q602.4@5649.8,1802.71 ; Q602.5@5592.28,1818.06 Q602.4@5639,1809.7 ; Q602.5@5592.43,1823.06 Q602.4@5633.77,1812.71 ; Q602.5@5592.5,1813.03 Q602.4@5649.8,1802.71 ; Q602.5@5592.58,1789.05 Q602.4@5631.56,1799.64 ; Q602.5@5592.73,1799.1 Q602.4@5639,1809.7 ; Q602.5@5592.82,1812.98 Q602.4@5627.13,1803.77 ; Q602.5@5592.86,1794.08 Q602.4@5622.13,1803.03 ; Q602.5@5592.89,1833.05 Q602.4@5633.05,1817.72 ; Q602.5@5592.95,1794.09 Q602.4@5627.13,1803.77 ; Q602.5@5593,1799.15 Q602.4@5636.27,1811 ; Q602.5@5593.04,1823.02 Q602.4@5636.27,1811 ; Q602.5@5593.13,1799.18 Q602.4@5642.59,1813.25 ; Q602.5@5593.17,1812.92 Q602.4@5622.13,1803.03 ; Q602.5@5593.19,1789.09 Q602.4@5649.8,1802.71 ; Q602.5@5593.34,1799.22 Q602.4@5633.77,1812.71 ; Q602.5@5593.33,1828.01 Q602.4@5642.59,1813.25 ; Q602.5@5593.39,1812.87 Q602.4@5631.56,1799.64 ; Q602.5@5593.43,1822.99 Q602.4@5639,1809.7 ; Q602.5@5593.57,1779.09 Q602.4@5629.24,1795.15 ; Q602.5@5593.6,1817.92 Q602.4@5649.8,1802.71 ; Q602.5@5593.84,1808.8 5573.95,1878.55 ; Q602.5@5593.97,1827.96 Q602.4@5633.77,1812.71 ; Q602.5@5594.11,1794.27 Q602.4@5639,1809.7 ; Q602.5@5594.13,1799.46 Q602.4@5633.05,1817.72 ; Q602.5@5594.24,1784.17 Q602.4@5631.56,1799.64 ; Q602.5@5594.23,1812.6 Q602.4@5629.24,1795.15 ; Q602.5@5594.47,1817.75 Q602.4@5627.13,1803.77 ; Q602.5@5594.59,1784.22 Q602.4@5649.8,1802.71 ; Q602.5@5594.59,1794.38 Q602.4@5636.27,1811 ; Q602.5@5594.69,1789.29 Q602.4@5627.13,1803.77 ; Q602.5@5594.69,1827.87 Q602.4@5636.27,1811 ; Q602.5@5594.74,1794.42 Q602.4@5642.59,1813.25 ; Q602.5@5594.78,1789.31 Q602.4@5622.13,1803.03 ; Q602.5@5595.06,1832.87 Q602.4@5642.59,1813.25 ; Q602.5@5595.13,1827.81 Q602.4@5639,1809.7 ; Q602.5@5595.21,1794.55 Q602.4@5633.77,1812.71 ; Q602.5@5595.19,1817.55 Q602.4@5622.13,1803.03 ; Q602.5@5595.33,1817.51 Q602.4@5631.56,1799.64 ; Q602.5@5595.54,1811.92 5637.51,1780.05 ; Q602.5@5596.01,1789.58 Q602.4@5639,1809.7 ; Q602.5@5596.13,1832.71 Q602.4@5633.77,1812.71 ; Q602.5@5596.43,1779.44 Q602.4@5649.8,1802.71 ; Q602.5@5596.56,1779.47 Q602.4@5631.56,1799.64 ; Q602.5@5596.53,1795.04 Q602.4@5633.05,1817.72 ; Q602.5@5596.73,1789.79 Q602.4@5636.27,1811 ; Q602.5@5596.76,1816.95 Q602.4@5629.24,1795.15 ; Q602.5@5596.82,1789.82 Q602.4@5642.59,1813.25 ; Q602.5@5596.81,1822.29 Q602.4@5627.13,1803.77 ; Q602.5@5596.92,1832.56 Q602.4@5636.27,1811 ; Q602.5@5597.08,1827.4 Q602.4@5649.8,1802.71 ; Q602.5@5597.15,1784.71 Q602.4@5627.13,1803.77 ; Q602.5@5597.36,1832.47 Q602.4@5639,1809.7 ; Q602.5@5597.54,1784.82 Q602.4@5622.13,1803.03 ; Q602.5@5597.64,1790.1 Q602.4@5633.77,1812.71 ; Q602.5@5597.86,1821.91 Q602.4@5631.56,1799.64 ; Q602.5@5598,1821.86 Q602.4@5622.13,1803.03 ; Q602.5@5598.42,1785.08 Q602.4@5639,1809.7 ; Q602.5@5598.67,1810.36 5573.95,1878.55 ; Q602.5@5598.76,1815.77 5637.51,1780.05 ; Q602.5@5599.36,1785.41 Q602.4@5642.59,1813.25 ; Q602.5@5599.41,1785.42 Q602.4@5636.27,1811 ; Q602.5@5599.45,1790.9 Q602.4@5633.05,1817.72 ; Q602.5@5599.45,1831.94 Q602.4@5649.8,1802.71 ; Q602.5@5599.87,1820.98 Q602.4@5629.24,1795.15 ; Q602.5@5599.83,1826.51 Q602.4@5627.13,1803.77 ; Q602.5@5600.33,1780.45 Q602.4@5627.13,1803.77 ; Q602.5@5600.62,1785.92 Q602.4@5633.77,1812.71 ; Q602.5@5600.97,1826.02 Q602.4@5631.56,1799.64 ; Q602.5@5601.16,1780.74 Q602.4@5622.13,1803.03 ; Q602.5@5601.34,1780.81 Q602.4@5639,1809.7 ; Q602.5@5601.59,1825.72 Q602.4@5622.13,1803.03 ; Q602.5@5602.36,1781.22 Q602.4@5642.59,1813.25 ; Q602.5@5602.36,1819.31 5637.51,1780.05 ; Q602.5@5602.61,1781.33 Q602.4@5636.27,1811 ; Q602.5@5602.89,1787.09 Q602.4@5633.05,1817.72 ; Q602.5@5603.52,1824.62 Q602.4@5629.24,1795.15 ; Q602.5@5603.54,1830.34 Q602.4@5627.13,1803.77 ; Q602.5@5604.15,1782.07 Q602.4@5633.77,1812.71 ; Q602.5@5604.64,1829.76 Q602.4@5631.56,1799.64 ; Q602.5@5605.94,1829.01 Q602.4@5622.13,1803.03 ; Q602.5@5606.31,1822.51 5637.51,1780.05 ; Q602.5@5606.82,1783.66 Q602.4@5633.05,1817.72 ; Q602.5@5607.71,1827.8 Q602.4@5629.24,1795.15 ; Q602.5@5610.59,1825.35 5637.51,1780.05 ; C659.2@5690.91,1776.66 5683,1794.04 ; C659.2@5695.57,1788.41 5671.95,1780.05 ; C659.2@5696.16,1773.6 5671.95,1780.05 ; C659.2@5700.91,1787.44 5683,1794.04 ; Q602.2@5497.86,1789.71 Q602.5@5526.63,1780.05 ; Q602.2@5497.86,1789.71 Q602.5@5526.63,1780.05 ; Q602.2@5497.86,1789.71 5553.7,1779.06 Q602.2@5497.86,1789.71 ; Q602.2@5497.86,1789.71 5538.61,1829.35 Q602.2@5497.86,1789.71 ; Q602.2@5497.86,1789.71 5554.43,1784.12 Q602.2@5497.86,1789.71 ; Q602.2@5497.86,1789.71 5542.01,1825.52 Q602.2@5497.86,1789.71 ; Q602.2@5497.86,1789.71 5554.7,1789.19 Q602.2@5497.86,1789.71 ; Q602.2@5497.86,1789.71 5545.02,1821.44 Q602.2@5497.86,1789.71 ; Q602.2@5497.86,1789.71 5554.52,1794.23 Q602.2@5497.86,1789.71 ; Q602.2@5497.86,1789.71 5547.65,1817.14 Q602.2@5497.86,1789.71 ; Q602.2@5497.86,1789.71 5553.9,1799.21 Q602.2@5497.86,1789.71 ; Q602.2@5497.86,1789.71 5549.87,1812.64 Q602.2@5497.86,1789.71 ; Q602.2@5499.25,1784.39 5556.33,1779.32 Q602.2@5499.25,1784.39 ; Q602.2@5499.25,1784.39 5536.48,1827.96 Q602.2@5499.25,1784.39 ; Q602.2@5499.25,1784.39 5556.56,1784.44 Q602.2@5499.25,1784.39 ; Q602.2@5499.25,1784.39 5540.21,1824.46 Q602.2@5499.25,1784.39 ; Q602.2@5499.25,1784.39 5556.33,1789.5 Q602.2@5499.25,1784.39 ; Q602.2@5499.25,1784.39 5543.6,1820.68 Q602.2@5499.25,1784.39 ; Q602.2@5499.25,1784.39 5555.66,1794.5 Q602.2@5499.25,1784.39 ; Q602.2@5499.25,1784.39 5546.62,1816.65 Q602.2@5499.25,1784.39 ; Q602.2@5499.25,1784.39 5554.56,1799.39 Q602.2@5499.25,1784.39 ; Q602.2@5499.25,1784.39 5549.25,1812.38 Q602.2@5499.25,1784.39 ; Q602.2@5500.63,1795.72 Q602.5@5526.63,1780.05 ; Q602.2@5500.63,1795.72 Q602.5@5526.63,1780.05 ; Q602.2@5500.63,1795.72 5550.63,1779.07 Q602.2@5500.63,1795.72 ; Q602.2@5500.63,1795.72 5540.39,1830.31 Q602.2@5500.63,1795.72 ; Q602.2@5500.63,1795.72 5552.02,1784.02 Q602.2@5500.63,1795.72 ; Q602.2@5500.63,1795.72 5543.57,1826.27 Q602.2@5500.63,1795.72 ; Q602.2@5500.63,1795.72 5552.9,1789.03 Q602.2@5500.63,1795.72 ; Q602.2@5500.63,1795.72 5546.31,1821.99 Q602.2@5500.63,1795.72 ; Q602.2@5500.63,1795.72 5553.3,1794.06 Q602.2@5500.63,1795.72 ; Q602.2@5500.63,1795.72 5548.62,1817.5 Q602.2@5500.63,1795.72 ; Q602.2@5500.63,1795.72 5553.22,1799.08 Q602.2@5500.63,1795.72 ; Q602.2@5500.63,1795.72 5550.47,1812.83 Q602.2@5500.63,1795.72 ; Q602.2@5500.63,1806.05 Q602.5@5526.63,1780.05 ; Q602.2@5500.63,1806.05 Q602.5@5548.82,1780.05 ; Q602.2@5500.63,1806.05 Q602.5@5547.61,1784.53 ; Q602.2@5500.63,1806.05 Q602.5@5551.83,1813.06 ; Q602.2@5501.97,1779.75 5558.76,1779.81 Q602.2@5501.97,1779.75 ; Q602.2@5501.97,1779.75 5534.45,1826.34 Q602.2@5501.97,1779.75 ; Q602.2@5501.97,1779.75 5558.53,1784.92 Q602.2@5501.97,1779.75 ; Q602.2@5501.97,1779.75 5538.51,1823.22 Q602.2@5501.97,1779.75 ; Q602.2@5501.97,1779.75 5557.84,1789.95 Q602.2@5501.97,1779.75 ; Q602.2@5501.97,1779.75 5542.25,1819.79 Q602.2@5501.97,1779.75 ; Q602.2@5501.97,1779.75 5556.71,1794.86 Q602.2@5501.97,1779.75 ; Q602.2@5501.97,1779.75 5545.64,1816.06 Q602.2@5501.97,1779.75 ; Q602.2@5501.97,1779.75 5555.17,1799.63 Q602.2@5501.97,1779.75 ; Q602.2@5501.97,1779.75 5548.67,1812.07 Q602.2@5501.97,1779.75 ; Q602.2@5503.23,1804.65 Q602.5@5551.17,1794.08 ; Q602.2@5503.23,1804.65 Q602.5@5552,1799.03 ; Q602.2@5504.12,1811.67 Q602.5@5548.82,1780.05 ; Q602.2@5504.12,1811.67 Q602.5@5550.99,1799.15 ; Q602.2@5504.64,1800.98 Q602.5@5526.63,1780.05 ; Q602.2@5504.64,1800.98 Q602.5@5526.63,1780.05 ; Q602.2@5504.64,1800.98 5547.47,1779.46 Q602.2@5504.64,1800.98 ; Q602.2@5504.64,1800.98 5541.98,1831.03 Q602.2@5504.64,1800.98 ; Q602.2@5504.64,1800.98 5549.54,1784.2 Q602.2@5504.64,1800.98 ; Q602.2@5504.64,1800.98 5545,1826.83 Q602.2@5504.64,1800.98 ; Q602.2@5504.64,1800.98 5551.07,1789.07 Q602.2@5504.64,1800.98 ; Q602.2@5504.64,1800.98 5547.52,1822.39 Q602.2@5504.64,1800.98 ; Q602.2@5504.64,1800.98 5552.07,1794.02 Q602.2@5504.64,1800.98 ; Q602.2@5504.64,1800.98 5549.54,1817.76 Q602.2@5504.64,1800.98 ; Q602.2@5504.64,1800.98 5552.53,1799.03 Q602.2@5504.64,1800.98 ; Q602.2@5504.64,1800.98 5551.05,1812.96 Q602.2@5504.64,1800.98 ; Q602.2@5505.44,1776.07 5560.9,1780.43 Q602.2@5505.44,1776.07 ; Q602.2@5505.44,1776.07 5532.65,1824.6 Q602.2@5505.44,1776.07 ; Q602.2@5505.44,1776.07 5560.27,1785.51 Q602.2@5505.44,1776.07 ; Q602.2@5505.44,1776.07 5537,1821.89 Q602.2@5505.44,1776.07 ; Q602.2@5505.44,1776.07 5559.18,1790.47 Q602.2@5505.44,1776.07 ; Q602.2@5505.44,1776.07 5541.04,1818.82 Q602.2@5505.44,1776.07 ; Q602.2@5505.44,1776.07 5557.65,1795.28 Q602.2@5505.44,1776.07 ; Q602.2@5505.44,1776.07 5544.77,1815.42 Q602.2@5505.44,1776.07 ; Q602.2@5505.44,1776.07 5555.71,1799.9 Q602.2@5505.44,1776.07 ; Q602.2@5505.44,1776.07 5548.15,1811.72 Q602.2@5505.44,1776.07 ; Q602.2@5507.2,1815.63 Q602.5@5548.82,1780.05 ; Q602.2@5508.42,1804.33 Q602.5@5526.63,1780.05 ; Q602.2@5508.42,1804.33 Q602.5@5526.63,1780.05 ; Q602.2@5508.42,1804.33 5545,1780.03 Q602.2@5508.42,1804.33 ; Q602.2@5508.42,1804.33 5542.99,1831.42 Q602.2@5508.42,1804.33 ; Q602.2@5508.42,1804.33 Q602.5@5547.62,1784.53 ; Q602.2@5508.42,1804.33 5545.95,1827.14 Q602.2@5508.42,1804.33 ; Q602.2@5508.42,1804.33 5549.66,1789.23 Q602.2@5508.42,1804.33 ; Q602.2@5508.42,1804.33 5548.35,1822.61 Q602.2@5508.42,1804.33 ; Q602.2@5508.42,1804.33 Q602.5@5551.13,1794.08 ; Q602.2@5508.42,1804.33 5550.19,1817.89 Q602.2@5508.42,1804.33 ; Q602.2@5508.42,1804.33 Q602.5@5552.02,1799.03 ; Q602.2@5508.42,1804.33 5551.47,1813.03 Q602.2@5508.42,1804.33 ; Q602.2@5508.42,1804.33 Q602.5@5547.62,1784.53 ; Q602.2@5508.42,1804.33 Q602.5@5551.13,1794.08 ; Q602.2@5508.42,1804.33 Q602.5@5552.02,1799.03 ; Q602.2@5510.65,1819.31 Q602.5@5548.82,1780.05 ; Q602.2@5512.77,1807.06 Q602.5@5526.63,1780.05 ; Q602.2@5512.77,1807.06 Q602.5@5526.63,1780.05 ; Q602.2@5512.77,1807.06 5542.43,1780.89 Q602.2@5512.77,1807.06 ; Q602.2@5512.77,1807.06 5543.72,1831.68 Q602.2@5512.77,1807.06 ; Q602.2@5512.77,1807.06 5545.63,1785.06 Q602.2@5512.77,1807.06 ; Q602.2@5512.77,1807.06 5546.71,1827.36 Q602.2@5512.77,1807.06 ; Q602.2@5512.77,1807.06 5548.22,1789.52 Q602.2@5512.77,1807.06 ; Q602.2@5512.77,1807.06 5549.06,1822.77 Q602.2@5512.77,1807.06 ; Q602.2@5512.77,1807.06 5550.17,1794.21 Q602.2@5512.77,1807.06 ; Q602.2@5512.77,1807.06 5550.78,1817.98 Q602.2@5512.77,1807.06 ; Q602.2@5512.77,1807.06 5551.5,1799.07 Q602.2@5512.77,1807.06 ; Q602.2@5512.77,1807.06 Q602.5@5551.86,1813.06 ; Q602.2@5512.77,1807.06 Q602.5@5551.86,1813.06 ; Q602.2@5514.45,1822.67 Q602.5@5548.82,1780.05 ; Q602.2@5517.65,1809.04 Q602.5@5526.63,1780.05 ; Q602.2@5517.65,1809.04 Q602.5@5526.63,1780.05 ; Q602.2@5517.65,1809.04 5539.7,1782.14 Q602.2@5517.65,1809.04 ; Q602.2@5517.65,1809.04 5543.99,1831.77 Q602.2@5517.65,1809.04 ; Q602.2@5517.65,1809.04 5543.56,1785.83 Q602.2@5517.65,1809.04 ; Q602.2@5517.65,1809.04 5547.16,1827.47 Q602.2@5517.65,1809.04 ; Q602.2@5517.65,1809.04 5546.73,1789.96 Q602.2@5517.65,1809.04 ; Q602.2@5517.65,1809.04 5549.57,1822.86 Q602.2@5517.65,1809.04 ; Q602.2@5517.65,1809.04 5549.21,1794.43 Q602.2@5517.65,1809.04 ; Q602.2@5517.65,1809.04 5551.25,1818.03 Q602.2@5517.65,1809.04 ; Q602.2@5517.65,1809.04 Q602.5@5551,1799.15 ; Q602.2@5517.65,1809.04 5552.2,1813.08 Q602.2@5517.65,1809.04 ; Q602.2@5517.65,1809.04 Q602.5@5551,1799.15 ; Q602.5@5526.63,1780.05 C659.2@5696.99,1780.05 ; Q602.5@5526.63,1780.05 5496.8,1774.44 Q602.5@5526.63,1780.05 ; Q602.5@5526.63,1780.05 5496.28,1779.68 Q602.5@5526.63,1780.05 ; Q602.5@5526.63,1780.05 5496.65,1784.8 Q602.5@5526.63,1780.05 ; 5573.95,1878.55 5658.46,1794.04 5683,1794.04 ; Q602.5@5595.15,1822.72 Q602.4@5633.41,1806.05 ; Q602.5@5595.15,1822.72 Q602.4@5633.41,1806.05 ; Q602.5@5595.13,1822.72 Q602.4@5649.8,1802.71 ; Q602.5@5604.13,1811 Q602.4@5629.24,1795.15 ; Q602.5@5604.13,1811 Q602.4@5633.05,1817.72 ; Q602.5@5604.13,1811 Q602.4@5631.56,1799.64 ; Q602.5@5604.13,1811 Q602.4@5633.77,1812.71 ; Q602.5@5604.13,1811 Q602.4@5633.41,1806.05 ; Q602.5@5620.4,1832.11 Q602.4@5622.13,1803.03 ; Q602.5@5620.4,1832.11 Q602.4@5642.59,1813.25 ; Q602.5@5620.4,1832.11 Q602.4@5627.13,1803.77 ; Q602.5@5620.4,1832.11 Q602.4@5639,1809.7 ; Q602.5@5620.4,1832.11 Q602.4@5633.41,1806.05 ; Q602.4@5633.41,1806.05 5600.43,1831.62 Q602.4@5633.41,1806.05 ; Q602.4@5633.41,1806.05 5600.43,1780.48 Q602.4@5633.41,1806.05 ; Q602.4@5633.41,1806.05 5597.49,1827.3 Q602.4@5633.41,1806.05 ; Q602.4@5633.41,1806.05 5597.49,1784.8 Q602.4@5633.41,1806.05 ; Q602.4@5633.41,1806.05 5595.15,1789.38 Q602.4@5633.41,1806.05 ; Q602.4@5633.41,1806.05 5593.41,1817.95 Q602.4@5633.41,1806.05 ; Q602.4@5633.41,1806.05 5593.41,1794.15 Q602.4@5633.41,1806.05 ; Q602.4@5633.41,1806.05 5592.27,1813.05 Q602.4@5633.41,1806.05 ; Q602.4@5633.41,1806.05 5592.27,1799.05 Q602.4@5633.41,1806.05 ; Q602.4@5633.77,1812.71 5591.15,1813.06 Q602.4@5642.59,1813.25 ; 5671.95,1780.05 C659.2@5696.99,1781.05 ; 5683,1794.04 C659.2@5696.99,1780.05 ; 5683,1794.04 5659.56,1815.89 5683,1794.04 ; 5683,1794.04 5650.96,1794.61 5683,1794.04 ; 5683,1794.04 5656.42,1811.94 5683,1794.04 ; 5683,1794.04 5651.45,1799.64 5683,1794.04 ; 5683,1794.04 5653.29,1806.05 5683,1794.04 ; 5683,1794.04 C659.2@5696.99,1781.05 ; C659.2@5696.99,1780.05 C659.2@5696.99,1781.05
  Top w8: v1@5488.44,2041.89 5505.99,2051.05 ; v1(5491.99,2037.05) 5505.99,2051.05 ; v1@5496.83,2033.5 5505.99,2051.05 ; v1@5503.96,2306.87 U609.54@5531.76,2301.26 ; v1@5504.11,2294.94 U609.54@5531.76,2301.26 ; v1@5504.3,2306.83 U609.54@5520.93,2301.26 ; v1@5504.55,2295.01 U609.54@5520.93,2301.26 ; U609.63@5520.93,2124.1 5505.99,2114.05 ; U609.63@5531.76,2124.1 5516.04,2124.1 5505.99,2114.05 ; v1@5590.72,2034.94 C651.1@5594,2007.94 ; v1@5590.77,2034.27 C651.1@5596.72,2010.28 ; v1@5590.74,2035.5 5596.72,2071 v1@5602.7,2035.5 ; v1@5590.75,2035.55 U609.3@5596.72,2067.99 ; v1@5590.88,2033.62 C651.1@5600,2008 ; v1@5591.33,2032.38 C651.1@5605.84,2009.38 ; v1@5596.72,2039.07 U609.3@5596.72,2067.99 ; U609.3@5596.72,2078.82 v1(5596.72,2035) ; v1@5602.56,2036.38 C651.1@5605.84,2009.38 ; v1@5602.59,2033.74 C651.1@5594,2007.94 ; v1@5602.68,2034.27 C651.1@5596.72,2010.28 ; v1@5602.72,2035.06 C651.1@5600,2008 ; v1@5602.7,2035.55 U609.3@5596.72,2067.99 ; v1(5503.4,2300.9) v1@5508.4,2301.26 ; v1(5503.4,2300.9) U609.54@5531.76,2301.26 ; v1(5503.4,2300.9) U609.54@5520.93,2301.26 ; 5505.99,2051.05 5505.99,2114.05 ; v1@5508.4,2301.26 U609.54@5531.76,2301.26 ; v1@5508.4,2301.26 U609.54@5520.93,2301.26 ; C651.1@5594,2007.94 v1(5596.72,2035) ; C651.1@5594,2007.94 v1(5596.72,2035) ; C651.1@5596.72,2010.28 5600,2007 C651.1@5600,2008 ; C651.1@5596.72,2010.28 v1(5596.72,2035) ; C651.1@5596.72,2010.28 v1(5596.72,2035) ; v1(5596.72,2035) C651.1@5605.84,2009.38 ; v1(5596.72,2035) C651.1@5600,2008 ; v1(5596.72,2035) U609.3@5596.72,2067.99
  Top w10: U609.54@5531.76,2301.26 5575.68,2301.26 ; U609.54@5542.59,2301.26 5575.68,2301.26 ; 5558.48,2491.3 C650.1@5528.99,2524.05 5530,2523.04 5530,2519.77 5596.99,2452.78 ; 5575.91,2301.04 5575.68,2301.26 ; 5577.99,2117.05 5589.99,2105.05 5596.72,2105.05 ; 5584.99,2379.05 5596.72,2379.05 ; U609.3@5596.72,2078.82 5596.72,2105.05 ; U609.3@5596.72,2089.65 5596.72,2105.05 ; 5596.72,2379.53 U609.46@5596.72,2414.45 ; U609.46@5596.72,2436.11 5596.99,2452.78 ; 5754.2,2379.53 U609.38@5754.2,2414.45 ; U609.38@5754.2,2436.11 5754.2,2471.03 ; 5758.34,2490.19 C664.1@5785.99,2524.05 ; C664.1@5785.99,2525.05 5785.99,2519.84 5786.99,2518.84 5754.2,2486.05 U609.38@5754.2,2425.28 5754.2,2379.05 5596.72,2379.05 ; 5596.72,2379.05 U609.46@5596.72,2425.28 5596.99,2425.55 5596.99,2452.78
  Top w12: C643.1@5441.99,2037.05 v1(5491.99,2037.05) ; C643.1@5442.99,2042.05 v1@5489.69,2037.05 ; C643.1@5443.99,2037.05 v1(5491.99,2037.05) ; C643.1@5444.17,2041.92 v1(5491.99,2037.05)
  Top w20: C637.1@5428.44,1817.05 5441.99,1896.48 ; C637.1@5441.99,1806.05 5441.99,2037.05 C639.1@5442.99,1972.05 ; 5441.99,1867.01 C638.1@5442.99,1937.05 ; C639.1@5441.99,1971.96 C643.1@5442.99,2042.05 C639.1@5442.99,1972.05 ; 5441.99,2007.09 C638.1@5442.99,1937.05 ; Q602.4@5643.35,1806.05 5644.35,1805.05 Q602.4@5666.99,1805.05 ; C638.1@5442.99,1937.05 C639.1@5442.99,1972.05 ; C638.1@5442.99,1937.05 5441.99,1902.01 C639.1@5442.99,1972.05 ; Q602.4@5666.99,1805.05 5682.02,1790.02 ; Q602.4@5666.99,1805.05 C659.2@5696.99,1781.05 ; 5682.02,1790.02 5653.29,1806.05 C659.2@5696.99,1781.05 ; 5682.02,1790.02 C659.2@5696.99,1781.05 ; 5682.02,1790.02 C659.2@5696.99,1781.05 ; 5682.02,1790.02 C659.2@5696.99,1781.05 ; 5682.07,1790.02 5692.04,1780.05 5696.99,1780.05 C659.2@5696.99,1781.05 ; 5682.07,1790.02 C659.2@5696.99,1781.05 ; 5682.07,1790.02 C659.2@5696.99,1781.05
  Top w30: C637.1@5441.99,1806.05 C637.1@5428.44,1806.05 ; C637.1@5428.44,1806.05 Q602.2@5500.63,1806.05 C637.1@5428.44,1806.05
  Bottom w15: C769.1@5472.5,2302.5 C769.1@5473.5,2302.5 ; C769.1@5473.5,2302.5 5501.8,2302.5 v1(5503.4,2300.9) C769.1@5473.5,2302.5
  Bottom w16: 5536.72,2035 v1(5596.72,2035) 5494.04,2035 v1(5491.99,2037.05) 5552.15,2035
